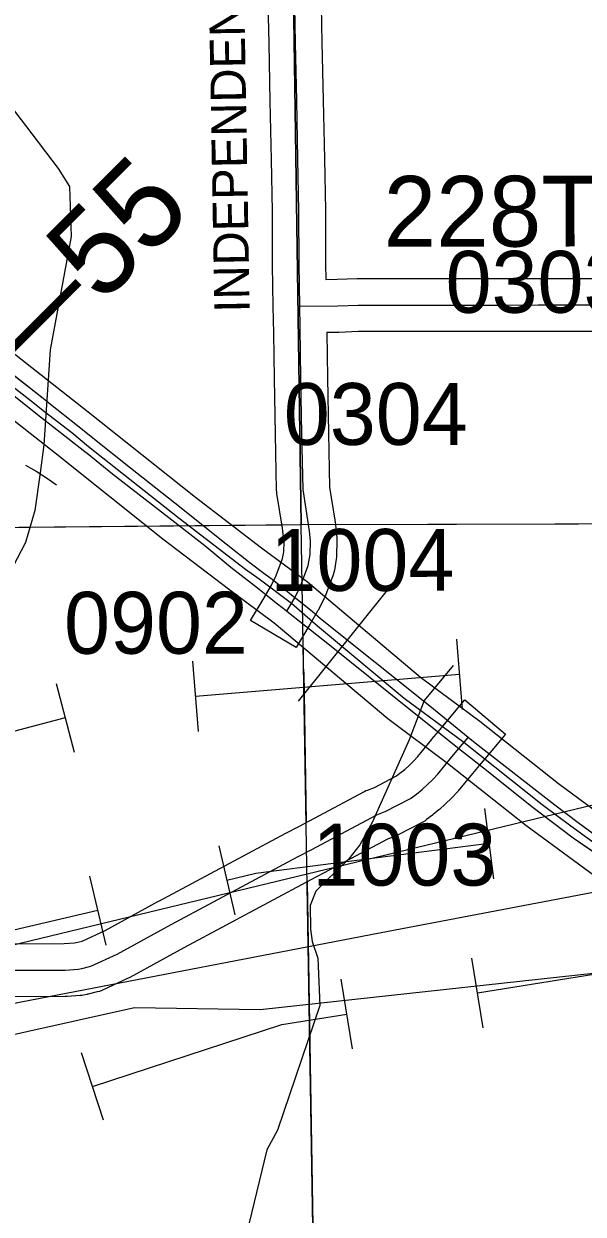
# Model space of a CAD drawing. Extents: x 23.6 to 68.7, y -63 to -29.
# Drawn here: x 41.355 to 41.988, y -47.394 to -46.047 of the extents above; entities that cross this region are included whole.
import ezdxf

# ---------------------------------------------------------------- set-up
doc = ezdxf.new("R2010")
doc.units = 0
for name, color, linetype in [('tdCoDivCarto', 7, 'Continuous'), ('tdCoHydroRiver', 7, 'Continuous'), ('tdCoPipe', 7, 'Continuous'), ('tdCoPipe1', 7, 'Continuous'), ('tdCoPipe2', 7, 'Continuous'), ('tdCoPipe3', 7, 'Continuous'), ('tdCoPriCL', 7, 'Continuous'), ('tdCoPriDiv', 7, 'Continuous'), ('tdCoPrimary', 7, 'Continuous'), ('tdCoPropPend', 7, 'Continuous'), ('tdCoSecRdNmbr', 7, 'Continuous'), ('tdCoSecRdTxt', 7, 'Continuous'), ('tdCoSecRteBand', 7, 'Continuous'), ('tdCoSecRteCL', 7, 'Continuous'), ('tdCoSectLine', 7, 'Continuous'), ('tdCoSectLinePart', 7, 'Continuous'), ('tdCoSurfGravel', 7, 'Continuous'), ('tdCoTwpBndry', 7, 'Continuous'), ('tdCoTwpBndryShd', 7, 'Continuous'), ('tdStHwyPriRefPost1', 7, 'Continuous'), ('tdStHwyPriRefPost5', 7, 'Continuous')]:
    doc.layers.add(name, color=color, linetype=linetype)

msp = doc.modelspace()

# ---------------------------------------------------------------- linework, layer by layer
at = {"layer": 'tdCoDivCarto'}
for p, q in [((41.3783, -46.4721), (41.3213, -46.4277)), ((41.3162, -46.4457), (41.3645, -46.4842)), ((41.3645, -46.4842), (41.3737, -46.4914)), ((41.3848, -46.4773), (41.3783, -46.4721)), ((41.4153, -46.5016), (41.3848, -46.4773)), ((41.4153, -46.5016), (41.3848, -46.4773)), ((41.3737, -46.4914), (41.4044, -46.5154)), ((41.3737, -46.4914), (41.4044, -46.5154)), ((41.4346, -46.517), (41.4153, -46.5016)), ((41.4346, -46.517), (41.4153, -46.5016)), ((41.4044, -46.5154), (41.4238, -46.5306)), ((41.4044, -46.5154), (41.4238, -46.5306)), ((41.4754, -46.5495), (41.4346, -46.517)), ((41.4238, -46.5306), (41.4262, -46.5325)), ((41.4262, -46.5325), (41.455, -46.5559)), ((41.5329, -46.5949), (41.4754, -46.5495)), ((41.455, -46.5559), (41.5224, -46.608)), ((41.5748, -46.6285), (41.5329, -46.5949)), ((41.5224, -46.608), (41.5598, -46.6371)), ((41.6091, -46.6556), (41.5748, -46.6285)), ((41.5598, -46.6371), (41.5892, -46.6615)), ((41.6111, -46.6571), (41.6091, -46.6556)), ((41.6263, -46.6685), (41.6111, -46.6571)), ((41.6263, -46.6685), (41.6111, -46.6571)), ((41.5892, -46.6615), (41.6007, -46.6705)), ((41.6007, -46.6705), (41.6157, -46.6823)), ((41.6007, -46.6705), (41.6157, -46.6823)), ((41.6357, -46.6756), (41.6263, -46.6685)), ((41.6157, -46.6823), (41.642, -46.7029)), ((41.6616, -46.6961), (41.6357, -46.6756)), ((41.6625, -46.6968), (41.6616, -46.6961)), ((41.6811, -46.7116), (41.6625, -46.6968)), ((41.642, -46.7029), (41.6516, -46.7105)), ((41.6516, -46.7105), (41.6526, -46.7113)), ((41.6526, -46.7113), (41.7009, -46.7495)), ((41.6908, -46.7199), (41.6811, -46.7116)), ((41.8143, -46.8187), (41.6908, -46.7199)), ((41.7009, -46.7495), (41.7912, -46.822)), ((41.7912, -46.822), (41.8474, -46.8666)), ((41.8578, -46.8541), (41.8143, -46.8187)), ((41.8659, -46.8607), (41.8578, -46.8541)), ((41.9561, -46.9307), (41.8659, -46.8607)), ((41.8474, -46.8666), (41.8804, -46.8928)), ((41.8804, -46.8928), (41.93, -46.9325)), ((41.93, -46.9325), (41.9766, -46.9678)), ((41.9823, -46.9509), (41.9561, -46.9307)), ((42.0163, -46.9758), (41.9823, -46.9509)), ((41.9766, -46.9678), (42.036, -47.0085))]:
    msp.add_line(p, q, dxfattribs=at)
for points in [[(41.3848, -46.4773), (41.3783, -46.4721), (41.3213, -46.4277)], [(41.3848, -46.4773), (41.3783, -46.4721), (41.3213, -46.4277)], [(41.3848, -46.4773), (41.3783, -46.4721), (41.3213, -46.4277)], [(41.3162, -46.4457), (41.3645, -46.4842), (41.3737, -46.4914)], [(41.3162, -46.4457), (41.3645, -46.4842), (41.3737, -46.4914)], [(41.3162, -46.4457), (41.3645, -46.4842), (41.3737, -46.4914)], [(41.4153, -46.5016), (41.3848, -46.4773)], [(41.4153, -46.5016), (41.3848, -46.4773)], [(41.3737, -46.4914), (41.4044, -46.5154)], [(41.3737, -46.4914), (41.4044, -46.5154)], [(41.4346, -46.517), (41.4153, -46.5016)], [(41.4346, -46.517), (41.4153, -46.5016)], [(41.4044, -46.5154), (41.4238, -46.5306)], [(41.4044, -46.5154), (41.4238, -46.5306)], [(41.6111, -46.6571), (41.6091, -46.6556), (41.5748, -46.6285), (41.5329, -46.5949), (41.4754, -46.5495), (41.4346, -46.517)], [(41.6111, -46.6571), (41.6091, -46.6556), (41.5748, -46.6285), (41.5329, -46.5949), (41.4754, -46.5495), (41.4346, -46.517)], [(41.6111, -46.6571), (41.6091, -46.6556), (41.5748, -46.6285), (41.5329, -46.5949), (41.4754, -46.5495), (41.4346, -46.517)], [(41.4238, -46.5306), (41.4262, -46.5325), (41.455, -46.5559), (41.5224, -46.608), (41.5598, -46.6371), (41.5892, -46.6615), (41.6007, -46.6705)], [(41.4238, -46.5306), (41.4262, -46.5325), (41.455, -46.5559), (41.5224, -46.608), (41.5598, -46.6371), (41.5892, -46.6615), (41.6007, -46.6705)], [(41.4238, -46.5306), (41.4262, -46.5325), (41.455, -46.5559), (41.5224, -46.608), (41.5598, -46.6371), (41.5892, -46.6615), (41.6007, -46.6705)], [(41.6263, -46.6685), (41.6111, -46.6571)], [(41.6263, -46.6685), (41.6111, -46.6571)], [(41.6007, -46.6705), (41.6157, -46.6823)], [(41.6007, -46.6705), (41.6157, -46.6823)], [(41.6625, -46.6968), (41.6616, -46.6961), (41.6357, -46.6756), (41.6263, -46.6685)], [(41.6625, -46.6968), (41.6616, -46.6961), (41.6357, -46.6756), (41.6263, -46.6685)], [(41.6625, -46.6968), (41.6616, -46.6961), (41.6357, -46.6756), (41.6263, -46.6685)], [(41.6157, -46.6823), (41.642, -46.7029), (41.6516, -46.7105)], [(41.6157, -46.6823), (41.642, -46.7029), (41.6516, -46.7105)], [(41.6157, -46.6823), (41.642, -46.7029), (41.6516, -46.7105)], [(42.157, -47.0688), (42.1053, -47.0353), (42.0163, -46.9758), (41.9823, -46.9509), (41.9561, -46.9307), (41.8659, -46.8607), (41.8578, -46.8541), (41.8143, -46.8187), (41.6908, -46.7199), (41.6811, -46.7116), (41.6625, -46.6968)], [(42.157, -47.0688), (42.1053, -47.0353), (42.0163, -46.9758), (41.9823, -46.9509), (41.9561, -46.9307), (41.8659, -46.8607), (41.8578, -46.8541), (41.8143, -46.8187), (41.6908, -46.7199), (41.6811, -46.7116), (41.6625, -46.6968)], [(42.157, -47.0688), (42.1053, -47.0353), (42.0163, -46.9758), (41.9823, -46.9509), (41.9561, -46.9307), (41.8659, -46.8607), (41.8578, -46.8541), (41.8143, -46.8187), (41.6908, -46.7199), (41.6811, -46.7116), (41.6625, -46.6968)], [(41.6516, -46.7105), (41.6526, -46.7113), (41.7009, -46.7495), (41.7912, -46.822), (41.8474, -46.8666), (41.8804, -46.8928), (41.93, -46.9325), (41.9766, -46.9678), (42.036, -47.0085), (42.0696, -47.0311), (42.1307, -47.0723), (42.1477, -47.0833)], [(41.6516, -46.7105), (41.6526, -46.7113), (41.7009, -46.7495), (41.7912, -46.822), (41.8474, -46.8666), (41.8804, -46.8928), (41.93, -46.9325), (41.9766, -46.9678), (42.036, -47.0085), (42.0696, -47.0311), (42.1307, -47.0723), (42.1477, -47.0833)], [(41.6516, -46.7105), (41.6526, -46.7113), (41.7009, -46.7495), (41.7912, -46.822), (41.8474, -46.8666), (41.8804, -46.8928), (41.93, -46.9325), (41.9766, -46.9678), (42.036, -47.0085), (42.0696, -47.0311), (42.1307, -47.0723), (42.1477, -47.0833)]]:
    msp.add_lwpolyline(points, dxfattribs=at)
at = {"layer": 'tdCoHydroRiver'}
for points in [[(41.3055, -46.0959), (41.3567, -46.1617), (41.3934, -46.2103), (41.4062, -46.2307), (41.4084, -46.2875), (41.3843, -46.4156), (41.3774, -46.523), (41.373, -46.5546), (41.3671, -46.5973), (41.3564, -46.6337), (41.313, -46.7162)], [(41.8407, -46.7727), (41.808, -46.8125), (41.791, -46.8568), (41.7493, -46.9504), (41.7353, -46.9758), (41.7228, -46.9917), (41.6963, -47.0172), (41.6853, -47.0283), (41.6791, -47.0442), (41.6794, -47.071), (41.6811, -47.0852), (41.6876, -47.1041), (41.6897, -47.1577), (41.6421, -47.2987), (41.6297, -47.3209), (41.6039, -47.4285)]]:
    msp.add_lwpolyline(points, dxfattribs=at)
at = {"layer": 'tdCoPipe'}
for points in [[(46.103, -46.1798), (45.5856, -46.2895), (44.9769, -46.2032), (43.6255, -46.1712), (43.2532, -46.7297), (42.6847, -46.7777), (42.3107, -46.833), (42.0115, -46.9277), (40.9251, -47.1899), (40.1113, -47.3197), (39.6484, -47.4608), (39.1832, -47.451), (38.6235, -47.6839), (38.1571, -47.7224), (37.6167, -48.0396), (37.0534, -48.166), (36.1696, -48.1779)], [(46.1338, -46.2277), (45.7767, -46.3352), (44.9255, -46.5097), (44.1163, -46.6777), (43.3869, -46.8204), (42.92, -46.8308), (42.5619, -46.8739), (42.338, -46.9172), (42.051, -47.0197), (41.7672, -47.0738), (41.3515, -47.1539), (40.3824, -47.3522), (40.1423, -47.3856), (39.6233, -47.5255), (39.2125, -47.5311), (38.6525, -47.7459), (38.1901, -47.7844), (37.6663, -48.1355), (36.7826, -48.2843), (36.2006, -48.2399)], [(46.1215, -46.3345), (45.8873, -46.3578), (45.2643, -46.5112), (44.7329, -46.6291), (43.8936, -46.7934), (43.3419, -46.8915), (42.6259, -46.9958), (42.1065, -47.1095), (41.6222, -47.1623), (41.4799, -47.1602), (40.1315, -47.4603), (39.5684, -47.6007), (39.2033, -47.5875), (37.667, -48.1838), (36.3602, -48.453)]]:
    msp.add_lwpolyline(points, dxfattribs=at)
at = {"layer": 'tdCoPipe1'}
for p, q in [((41.8748, -47.1829), (41.8621, -47.1038)), ((41.7267, -47.2067), (41.714, -47.1276)), ((41.445, -47.2873), (41.4201, -47.2112))]:
    msp.add_line(p, q, dxfattribs=at)
for points in [[(41.8685, -47.1433), (42.1647, -47.0957)], [(41.4325, -47.2493), (41.647, -47.179), (41.7204, -47.1672)]]:
    msp.add_lwpolyline(points, dxfattribs=at)
at = {"layer": 'tdCoPipe2'}
for p, q in [((41.8762, -46.9345), (41.8865, -47.014)), ((41.5753, -46.9769), (41.5935, -47.0549)), ((41.4292, -47.011), (41.4475, -47.0891))]:
    msp.add_line(p, q, dxfattribs=at)
for points in [[(41.8813, -46.9742), (41.6174, -47.0082), (41.5844, -47.0159)], [(41.4384, -47.0501), (41.1462, -47.1184)]]:
    msp.add_lwpolyline(points, dxfattribs=at)
at = {"layer": 'tdCoPipe3'}
for p, q in [((41.8446, -46.7428), (41.8512, -46.8227)), ((41.5456, -46.7677), (41.5522, -46.8476)), ((41.3913, -46.7933), (41.4117, -46.8708))]:
    msp.add_line(p, q, dxfattribs=at)
for points in [[(41.8479, -46.7828), (41.5489, -46.8077)], [(41.4015, -46.8321), (41.1115, -46.9087)]]:
    msp.add_lwpolyline(points, dxfattribs=at)
at = {"layer": 'tdCoPriCL'}
msp.add_lwpolyline([(41.2709, -46.4021), (41.3594, -46.4707), (41.378, -46.4853), (41.4089, -46.5093), (41.4279, -46.5248), (41.5305, -46.606), (41.6058, -46.6636), (41.6212, -46.6749), (41.6577, -46.7023), (41.6728, -46.7153), (41.6873, -46.7279), (41.7853, -46.8096), (41.8528, -46.8596), (41.9416, -46.93), (41.974, -46.9544), (42.0125, -46.982)], dxfattribs=at)
at = {"layer": 'tdCoPriDiv'}
for points in [[(41.1985, -46.3057), (41.4276, -46.4858), (41.549, -46.5824), (41.6238, -46.6396), (41.6758, -46.6782), (41.8039, -46.786), (41.8711, -46.8358), (41.96, -46.9062), (42.0293, -46.9571), (42.1222, -47.0214), (42.1671, -47.0506), (42.2356, -47.0929), (42.268, -47.1165), (42.6776, -47.3766), (42.7226, -47.4074)], [(42.6445, -47.4267), (42.2354, -47.1669), (42.2017, -47.1425), (42.1364, -47.1022), (42.0886, -47.0712), (41.9957, -47.0069), (41.9233, -46.9537), (41.8346, -46.8835), (41.7668, -46.8332), (41.6381, -46.725), (41.5879, -46.6876), (41.5121, -46.6297), (41.3902, -46.5327), (41.163, -46.3542)]]:
    msp.add_lwpolyline(points, dxfattribs=at)
at = {"layer": 'tdCoPrimary'}
for p, q in [((41.4153, -46.5016), (41.3848, -46.4773)), ((41.4153, -46.5016), (41.3848, -46.4773)), ((41.3737, -46.4914), (41.4044, -46.5154)), ((41.3737, -46.4914), (41.4044, -46.5154)), ((41.4346, -46.517), (41.4153, -46.5016)), ((41.4346, -46.517), (41.4153, -46.5016)), ((41.4044, -46.5154), (41.4238, -46.5306)), ((41.4044, -46.5154), (41.4238, -46.5306)), ((41.6263, -46.6685), (41.6111, -46.6571)), ((41.6263, -46.6685), (41.6111, -46.6571)), ((41.6007, -46.6705), (41.6157, -46.6823)), ((41.6007, -46.6705), (41.6157, -46.6823))]:
    msp.add_line(p, q, dxfattribs=at)
for points in [[(41.3848, -46.4773), (41.3783, -46.4721), (41.3213, -46.4277)], [(41.3848, -46.4773), (41.3783, -46.4721), (41.3213, -46.4277)], [(42.0163, -46.9758), (41.9823, -46.9509), (41.9561, -46.9307), (41.8659, -46.8607), (41.8578, -46.8541), (41.8143, -46.8187), (41.6908, -46.7199), (41.6811, -46.7116), (41.6625, -46.6968), (41.6616, -46.6961), (41.6357, -46.6756), (41.6263, -46.6685), (41.6111, -46.6571), (41.6091, -46.6556), (41.5748, -46.6285), (41.5329, -46.5949), (41.4754, -46.5495), (41.4346, -46.517), (41.4153, -46.5016), (41.3848, -46.4773), (41.3783, -46.4721), (41.3213, -46.4277)], [(41.3162, -46.4457), (41.3645, -46.4842), (41.3737, -46.4914)], [(41.3162, -46.4457), (41.3645, -46.4842), (41.3737, -46.4914)], [(41.3162, -46.4457), (41.3645, -46.4842), (41.3737, -46.4914), (41.4044, -46.5154), (41.4238, -46.5306), (41.4262, -46.5325), (41.455, -46.5559), (41.5224, -46.608), (41.5598, -46.6371), (41.5892, -46.6615), (41.6007, -46.6705), (41.6157, -46.6823), (41.642, -46.7029), (41.6516, -46.7105), (41.6526, -46.7113), (41.7009, -46.7495), (41.7912, -46.822), (41.8474, -46.8666), (41.8804, -46.8928), (41.93, -46.9325), (41.9766, -46.9678), (42.036, -47.0085)], [(41.6111, -46.6571), (41.6091, -46.6556), (41.5748, -46.6285), (41.5329, -46.5949), (41.4754, -46.5495), (41.4346, -46.517)], [(41.6111, -46.6571), (41.6091, -46.6556), (41.5748, -46.6285), (41.5329, -46.5949), (41.4754, -46.5495), (41.4346, -46.517)], [(41.4238, -46.5306), (41.4262, -46.5325), (41.455, -46.5559), (41.5224, -46.608), (41.5598, -46.6371), (41.5892, -46.6615), (41.6007, -46.6705)], [(41.4238, -46.5306), (41.4262, -46.5325), (41.455, -46.5559), (41.5224, -46.608), (41.5598, -46.6371), (41.5892, -46.6615), (41.6007, -46.6705)], [(41.6625, -46.6968), (41.6616, -46.6961), (41.6357, -46.6756), (41.6263, -46.6685)], [(41.6625, -46.6968), (41.6616, -46.6961), (41.6357, -46.6756), (41.6263, -46.6685)], [(41.6157, -46.6823), (41.642, -46.7029), (41.6516, -46.7105)], [(41.6157, -46.6823), (41.642, -46.7029), (41.6516, -46.7105)], [(42.157, -47.0688), (42.1053, -47.0353), (42.0163, -46.9758), (41.9823, -46.9509), (41.9561, -46.9307), (41.8659, -46.8607), (41.8578, -46.8541), (41.8143, -46.8187), (41.6908, -46.7199), (41.6811, -46.7116), (41.6625, -46.6968)], [(42.157, -47.0688), (42.1053, -47.0353), (42.0163, -46.9758), (41.9823, -46.9509), (41.9561, -46.9307), (41.8659, -46.8607), (41.8578, -46.8541), (41.8143, -46.8187), (41.6908, -46.7199), (41.6811, -46.7116), (41.6625, -46.6968)], [(41.6516, -46.7105), (41.6526, -46.7113), (41.7009, -46.7495), (41.7912, -46.822), (41.8474, -46.8666), (41.8804, -46.8928), (41.93, -46.9325), (41.9766, -46.9678), (42.036, -47.0085), (42.0696, -47.0311), (42.1307, -47.0723), (42.1477, -47.0833)], [(41.6516, -46.7105), (41.6526, -46.7113), (41.7009, -46.7495), (41.7912, -46.822), (41.8474, -46.8666), (41.8804, -46.8928), (41.93, -46.9325), (41.9766, -46.9678), (42.036, -47.0085), (42.0696, -47.0311), (42.1307, -47.0723), (42.1477, -47.0833)]]:
    msp.add_lwpolyline(points, dxfattribs=at)
at = {"layer": 'tdCoPropPend'}
for p, q in [((41.3567, -46.5461), (41.3687, -46.5527)), ((41.3687, -46.5527), (41.3816, -46.5613)), ((41.3816, -46.5613), (41.3915, -46.5682)), ((41.7676, -46.6858), (41.6655, -46.813))]:
    msp.add_line(p, q, dxfattribs=at)
at = {"layer": 'tdCoSecRteBand'}
for points in [[(42.0255, -46.3948), (41.9373, -46.3948), (41.8986, -46.395), (41.8985, -46.395), (41.8984, -46.395), (41.8317, -46.395), (41.8021, -46.395), (41.7337, -46.395), (41.7113, -46.3958), (41.7109, -46.3958), (41.7105, -46.3958), (41.6978, -46.3959), (41.6984, -46.4471), (41.6995, -46.51), (41.7009, -46.5708), (41.7069, -46.6085), (41.707, -46.6092), (41.7071, -46.6098), (41.7079, -46.6173), (41.7091, -46.6283), (41.7093, -46.6304), (41.7093, -46.6324), (41.7089, -46.6478), (41.7089, -46.6501), (41.7085, -46.6523), (41.7063, -46.6648), (41.7058, -46.6675), (41.7049, -46.6701), (41.6962, -46.6934), (41.6957, -46.6948), (41.695, -46.6962), (41.6885, -46.7094), (41.688, -46.7104), (41.6874, -46.7113), (41.6785, -46.7265), (41.6632, -46.7524), (41.6115, -46.722), (41.6268, -46.6961), (41.6352, -46.6818), (41.6405, -46.671), (41.6477, -46.6518), (41.649, -46.6442), (41.6493, -46.633), (41.6483, -46.624), (41.6475, -46.6172), (41.6413, -46.5782), (41.641, -46.5762), (41.6409, -46.5742), (41.6396, -46.5112), (41.6396, -46.5112), (41.6396, -46.5111), (41.6384, -46.4481), (41.6384, -46.448), (41.6384, -46.4479), (41.6378, -46.3966), (41.6376, -46.3966), (41.6372, -46.3667), (41.6363, -46.3198), (41.6363, -46.3195), (41.6363, -46.3193), (41.6362, -46.2586), (41.635, -46.2004), (41.635, -46.2004), (41.635, -46.2004), (41.6338, -46.1342), (41.6324, -46.069), (41.6324, -46.069), (41.6324, -46.069), (41.6311, -46.0074)], [(41.6911, -46.0062), (41.6923, -46.0677), (41.6938, -46.133), (41.6938, -46.133), (41.6938, -46.133), (41.695, -46.1993), (41.6962, -46.2577), (41.6962, -46.258), (41.6962, -46.2582), (41.6963, -46.3189), (41.6966, -46.3357), (41.6966, -46.3359), (41.7095, -46.3358), (41.7321, -46.335), (41.7327, -46.335), (41.7332, -46.335), (41.8021, -46.335), (41.8317, -46.335), (41.8984, -46.335), (41.9371, -46.3348), (41.9372, -46.3348), (41.9372, -46.3348), (42.0254, -46.3348)], [(41.2841, -47.0877), (41.4002, -47.0875), (41.4122, -47.0866), (41.4139, -47.0862), (41.4206, -47.0846), (41.4469, -47.0726), (41.5071, -47.0396), (41.5072, -47.0395), (41.5074, -47.0394), (41.6514, -46.9625), (41.6515, -46.9625), (41.6515, -46.9624), (41.6659, -46.9548), (41.7406, -46.9152), (41.7421, -46.9144), (41.7438, -46.9138), (41.7516, -46.9107), (41.7766, -46.8978), (41.7806, -46.8948), (41.7861, -46.8903), (41.7913, -46.8856), (41.7964, -46.8807), (41.8009, -46.8759), (41.8162, -46.857), (41.8163, -46.8569), (41.8165, -46.8567), (41.8244, -46.8473), (41.8348, -46.8348), (41.8541, -46.8118), (41.9001, -46.8504), (41.8808, -46.8734), (41.8703, -46.8858), (41.8626, -46.8951), (41.8467, -46.9146), (41.846, -46.9155), (41.8453, -46.9163), (41.8396, -46.9223), (41.8391, -46.9228), (41.8387, -46.9232), (41.8327, -46.929), (41.8323, -46.9294), (41.8318, -46.9298), (41.8257, -46.9354), (41.8252, -46.9358), (41.8247, -46.9362), (41.8183, -46.9415), (41.8178, -46.9419), (41.8173, -46.9422), (41.8107, -46.9472), (41.8087, -46.9488), (41.8064, -46.95), (41.7778, -46.9647), (41.7764, -46.9655), (41.7749, -46.9661), (41.7672, -46.9691), (41.6939, -47.0078), (41.6796, -47.0154), (41.5358, -47.0923), (41.4748, -47.1257), (41.4738, -47.1263), (41.4728, -47.1267), (41.4429, -47.1404), (41.4403, -47.1415), (41.4376, -47.1422), (41.4276, -47.1447), (41.4269, -47.1448), (41.4263, -47.1449), (41.4222, -47.1458), (41.4204, -47.1461), (41.4186, -47.1463), (41.4036, -47.1474), (41.4025, -47.1475), (41.4014, -47.1475), (41.2843, -47.1477)]]:
    msp.add_lwpolyline(points, dxfattribs=at)
at = {"layer": 'tdCoSecRteCL'}
for points in [[(41.6672, -46.3663), (41.6663, -46.3192), (41.6662, -46.2583), (41.665, -46.1998), (41.6638, -46.1336), (41.6623, -46.0684), (41.6611, -46.0068), (41.6601, -45.9452), (41.6591, -45.8802), (41.6577, -45.8106), (41.6568, -45.7476), (41.6556, -45.6709), (41.6551, -45.649)], [(41.6526, -46.7113), (41.6616, -46.6961), (41.6681, -46.6829), (41.6767, -46.6597), (41.6789, -46.6471), (41.6793, -46.6317), (41.6781, -46.6206), (41.6772, -46.6132), (41.6709, -46.5735), (41.6695, -46.5106), (41.6684, -46.4476), (41.6677, -46.3902), (41.6672, -46.3663)], [(41.6672, -46.3663), (41.7102, -46.3658), (41.7332, -46.365), (41.8021, -46.365), (41.8317, -46.365), (41.8984, -46.365), (41.9372, -46.3648), (42.0255, -46.3648), (42.0512, -46.3646), (42.1358, -46.3645), (42.1615, -46.3646)], [(41.2841, -47.1177), (41.4013, -47.1175), (41.4163, -47.1164), (41.4204, -47.1155), (41.4304, -47.1131), (41.4604, -47.0994), (41.5215, -47.0659), (41.6655, -46.9889), (41.6799, -46.9813), (41.7546, -46.9418), (41.764, -46.9381), (41.7926, -46.9233), (41.7992, -46.9183), (41.8056, -46.913), (41.8118, -46.9075), (41.8178, -46.9017), (41.8234, -46.8957), (41.8395, -46.876), (41.8474, -46.8666), (41.8578, -46.8541)]]:
    msp.add_lwpolyline(points, dxfattribs=at)
at = {"layer": 'tdCoSectLine'}
for points in [[(41.6548, -45.649), (41.6689, -46.6134)], [(40.6692, -46.6228), (41.6689, -46.6134)], [(41.6689, -46.6134), (42.6739, -46.6105)], [(41.6853, -47.6123), (41.6689, -46.6134)]]:
    msp.add_lwpolyline(points, dxfattribs=at)
at = {"layer": 'tdCoSectLinePart'}
for points in [[(40.6692, -46.6228), (41.6461, -46.6136)], [(41.7066, -46.6133), (42.6739, -46.6105)], [(41.6744, -46.9501), (41.671, -46.7419)], [(41.6853, -47.6123), (41.6755, -47.0174)]]:
    msp.add_lwpolyline(points, dxfattribs=at)
at = {"layer": 'tdCoSurfGravel'}
msp.add_line((41.8474, -46.8666), (41.8578, -46.8541), dxfattribs=at)
for points in [[(41.6781, -46.6206), (41.6772, -46.6132), (41.6709, -46.5735), (41.6695, -46.5106), (41.6684, -46.4476), (41.6677, -46.3902), (41.6672, -46.3663), (41.6663, -46.3192), (41.6662, -46.2583), (41.665, -46.1998), (41.6638, -46.1336), (41.6623, -46.0684), (41.6611, -46.0068), (41.6601, -45.9452), (41.6591, -45.8802), (41.6577, -45.8106), (41.6568, -45.7476), (41.6556, -45.6709), (41.6551, -45.649)], [(41.6672, -46.3663), (41.7102, -46.3658), (41.7332, -46.365), (41.8021, -46.365), (41.8317, -46.365), (41.8984, -46.365), (41.9372, -46.3648), (42.0255, -46.3648), (42.0512, -46.3646), (42.1358, -46.3645), (42.1615, -46.3646)], [(41.6526, -46.7113), (41.6616, -46.6961), (41.6681, -46.6829), (41.6767, -46.6597), (41.6789, -46.6471), (41.6793, -46.6317), (41.6781, -46.6206)], [(41.6799, -46.9813), (41.7546, -46.9418), (41.764, -46.9381), (41.7926, -46.9233), (41.7992, -46.9183), (41.8056, -46.913), (41.8118, -46.9075), (41.8178, -46.9017), (41.8234, -46.8957), (41.8395, -46.876), (41.8474, -46.8666)], [(41.2841, -47.1177), (41.4013, -47.1175), (41.4163, -47.1164), (41.4204, -47.1155), (41.4304, -47.1131), (41.4604, -47.0994), (41.5215, -47.0659), (41.6655, -46.9889), (41.6799, -46.9813)]]:
    msp.add_lwpolyline(points, dxfattribs=at)
at = {"layer": 'tdCoTwpBndry'}
for points in [[(41.6717, -46.7805), (41.6744, -46.9501)], [(41.6755, -47.0174), (41.6853, -47.6123), (42.1567, -47.6085)]]:
    msp.add_lwpolyline(points, dxfattribs=at)
at = {"layer": 'tdCoTwpBndryShd'}
msp.add_lwpolyline([(42.7117, -48.5753), (42.694, -47.6042), (41.6853, -47.6123), (41.6689, -46.6134), (41.6548, -45.649)], dxfattribs=at)

# ---------------------------------------------------------------- texts
at = {"layer": 'tdCoSecRdNmbr'}
for s, rotation, p in [('0303', 0.0327, (41.8323, -46.3737)), ('0304', 0.0326, (41.6491, -46.5232)), ('1004', 0.0326, (41.634, -46.6884)), ('0902', 0.0326, (41.4002, -46.7595)), ('1003', 0.0326, (41.6815, -47.0219))]:
    msp.add_text(s, height=0.07, rotation=rotation, dxfattribs=at).set_placement(p)
at = {"layer": 'tdCoSecRdTxt'}
for s, height, rotation, p in [('INDEPENDENCE AVE', 0.04, 91, (41.6105, -46.3732)), ('228TH ST', 0.08, 0.0675, (41.7622, -46.2989))]:
    msp.add_text(s, height=height, rotation=rotation, dxfattribs=at).set_placement(p)
at = {"layer": 'tdStHwyPriRefPost1'}
msp.add_text('‒‒55', height=0.1, rotation=45, dxfattribs=at).set_placement((41.3375, -46.4701))
at = {"layer": 'tdStHwyPriRefPost5'}
msp.add_text('‒‒55', height=0.1, rotation=45, dxfattribs=at).set_placement((41.3375, -46.4701))

doc.saveas('drawing.dxf')
